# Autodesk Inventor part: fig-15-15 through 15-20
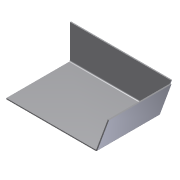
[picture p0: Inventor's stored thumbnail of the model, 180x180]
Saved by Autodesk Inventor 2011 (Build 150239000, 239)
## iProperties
Created: 2005-03
Part Number: fig-15-15 through 15-20
Document SubType Name: Sheet Metal
Designer: CADCIM
Manufacturer: Standard
Standards Organization: Custom
Density: 1 g/cm^3
Sheet Metal Rule: Default
Author: CADCIM
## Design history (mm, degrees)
node "Face2"
  sketch "Sketch1" dims "d32" = 0.5 (= BendRadius)
    geometry: L1 (-36, -8.631)-(4.238, -8.631); L2 (4.238, -8.631)-(4.238, 20); L3 (4.238, 20)-(-36, 20); L4 (-36, 20)-(-36, -8.631)
    constraints: 8 end point, 2 parallel, 1 horizontal, 1 perpendicular
node "Flange3"
node "Flange2"
feature "Corner2" dims "d36" = 2 (= CornerReliefSize), "d37" = 0.5 (= BendRadius), "d38" = 0.5 (= Thickness), "d39" = 0, "Thickness" = 0.5
body "Solid1"
face "Plate2" dims "Thickness" = 0.5
sketch "Sketch3" dims "CornerReliefSize" = 2 (= 4 x Thickness)
  geometry: L1 (39.356, 0)-(39.356, 15); L2 (39.356, 15)-(0, 15); 2 other entities
  constraints: 4 end point, 4 other
face "Plate4" dims "d18" = 0.5 (= BendReliefWidth), "d20" = 1 (= MinimumRemnant), "d22" = 15, "d23" = 90 deg, "d24" = 0.5 (= BendRadius), "d32" = 0.5 (= BendRadius), "Thickness" = 0.5, "CornerReliefSize" = 2 (= 4 x Thickness)
bend "Bend2" dims "d18" = 0.5 (= BendReliefWidth), "d19" = 0.25 (= BendReliefDepth), "d20" = 1 (= MinimumRemnant), "d21" = 0.5 (= BendRadius), "d22" = 15, "d23" = 90 deg, "d24" = 0.5 (= BendRadius), "SeamGap" = 0.01, "Thickness" = 0.5
node "FlatPattern"
sketch "Sketch4" dims "d32" = 0.5 (= BendRadius)
  geometry: L1 (28.631, 0)-(28.631, 15); L2 (28.631, 15)-(0, 15); 2 other entities
  constraints: 4 end point, 4 other
face "Plate5" dims "d29" = 0.5 (= BendReliefWidth), "d31" = 1 (= MinimumRemnant), "d32" = 0.5 (= BendRadius), "d33" = 15, "d34" = 70 deg, "d35" = 0.5 (= BendRadius), "Thickness" = 0.5
bend "Bend3" dims "d29" = 0.5 (= BendReliefWidth), "d30" = 0.25 (= BendReliefDepth), "d31" = 1 (= MinimumRemnant), "d32" = 0.5 (= BendRadius), "d33" = 15, "d34" = 70 deg, "d35" = 0.5 (= BendRadius), "SeamGap" = 0.01, "Thickness" = 0.5
feature "FlatPatternExtrusion2" dims "d0" = 0.5 (derived)
other parameters: "BendRadius" = 0.5 (= Thickness), "BendReliefWidth" = 0.5 (= Thickness), "BendReliefDepth" = 0.25 (= 0.5 x Thickness), "MinimumRemnant" = 1 (= 2 x Thickness), "TransitionRadius" = 0.5 (= BendRadius), "d0" = 0.5 (= BendRadius), "d10" = 0.5 (= BendRadius), "JacobiRadiusSize" = 0.5 (= Thickness), "GapSize" = 0.5 (= Thickness)
